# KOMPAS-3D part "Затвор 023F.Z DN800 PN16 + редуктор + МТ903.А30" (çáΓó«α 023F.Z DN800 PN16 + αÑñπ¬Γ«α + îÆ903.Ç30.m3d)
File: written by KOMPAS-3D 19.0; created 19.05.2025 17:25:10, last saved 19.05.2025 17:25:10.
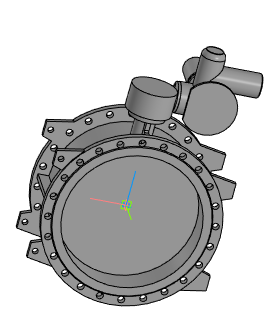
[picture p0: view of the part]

Document properties: Полное имя файла: Затвор 023F.Z DN800 PN16 + редуктор + МТ903.А30.a3d

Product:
- Part/product: Затвор 023F.Z DN800 PN16 + редуктор + МТ903.А30
    Масса: 956.862

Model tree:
1. Операция без истории:1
